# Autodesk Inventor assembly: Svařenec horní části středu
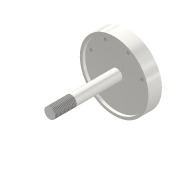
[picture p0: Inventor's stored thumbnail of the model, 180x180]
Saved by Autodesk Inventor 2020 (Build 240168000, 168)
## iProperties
Created: 2025-03
Part Number: Svařenec horní části středu
Document SubType Name: Assembly
Designer: doma
Author: doma
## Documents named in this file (3)
- C:\Users\doma\Desktop\Pásovka záloha\Workgroups\NotInProject\Svařenec horní části středu.iam
- C:\Users\doma\Desktop\Pásovka záloha\Workgroups\NotInProject\Vrch středu.ipt
- C:\Users\doma\Desktop\Pásovka záloha\Workgroups\NotInProject\Šroub středu.ipt
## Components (2 placed, 2 different names)
1. Vrch středu:1 — Proti sobě:1, Proti sobě:2
2. Šroub středu:1 — Proti sobě:1, Proti sobě:2
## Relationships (2: Mate 2)
- Proti sobě:1 [Mate]: Vrch středu:1 ↔ Šroub středu:1
- Proti sobě:2 [Mate]: Vrch středu:1 ↔ Šroub středu:1
